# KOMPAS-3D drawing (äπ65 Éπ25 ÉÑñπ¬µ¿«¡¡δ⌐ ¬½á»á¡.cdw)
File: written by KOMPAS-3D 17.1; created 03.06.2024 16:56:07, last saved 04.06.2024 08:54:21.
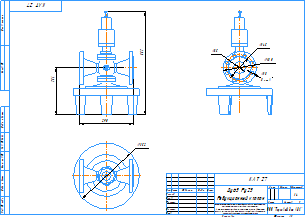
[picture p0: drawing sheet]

Sheet 1: A3, landscape

Title block, sheet 1: name: Ду65 Ру25 / Редукционный клапан; designation: КАТ 27; material: Внимание! Данный продукт является объектом авторского права ООО «Торговый Дом АДЛ». / Запрещается изменение, копирование, распространение / (в том числе путем копирования на другие сайты и ресурсы в Интернете) / или любое иное использование информации и объектов без предварительного / согласия правообладателя (ООО «Торговый Дом АДЛ»).; sheets: 1; organisation: ООО "Торговый дом АДЛ"; sheet format: A3; stored path: C:\Users\klav\Desktop\Модели\КАТ 27\KOMPAS 3D\Чертеж.cdw

Views: Вид 1, Спереди, Проекционный вид 2, Проекционный вид 3
Referenced files in C:\Users\klav\Desktop\Модели\КАТ 27\KOMPAS 3D\: КАТ27_ Ду65 Ру25 Редукционный клапан.m3d
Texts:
  Клочков АВ
  ООО АДЛ Групп
Dimensions and other numbers on the sheet: 552; 251; 290; 145; 180; 65; 18; 8 отв.; 352; 1:4; 1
